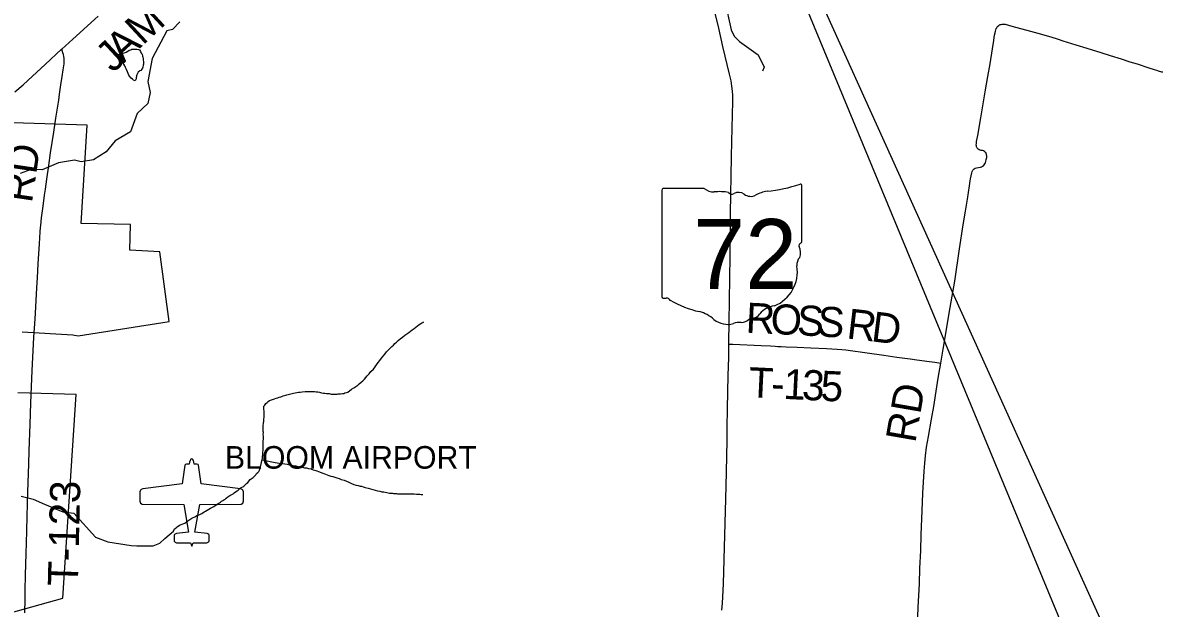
# Model space of a CAD drawing. Extents: x -5.4 to 49.9, y 13.2 to 48.4.
# Drawn here: x 28.445 to 30.593, y 41.82 to 42.924 of the extents above; entities that cross this region are included whole.
import ezdxf

# ---------------------------------------------------------------- set-up
doc = ezdxf.new("R2010")
doc.units = 0
for name, color, linetype in [('GM_X_Airport_Class_3', 7, 'Continuous'), ('GM_X_Airport_Location_Class_3', 7, 'Continuous'), ('GM_X_Airport_Text_Class_3', 7, 'Continuous'), ('GM_X_Corporation', 7, 'Continuous'), ('GM_X_County_Road', 7, 'Continuous'), ('GM_X_County_Road_Text', 7, 'Continuous'), ('GM_X_Minor_Lake', 7, 'Continuous'), ('GM_X_Minor_River', 7, 'Continuous'), ('GM_X_State_Location', 7, 'Continuous'), ('GM_X_State_Route', 7, 'Continuous'), ('GM_X_State_Shield', 7, 'Continuous'), ('GM_X_Township_Road', 7, 'Continuous'), ('GM_X_Township_Road_Text', 7, 'Continuous'), ('SH_Data', 7, 'Continuous')]:
    doc.layers.add(name, color=color, linetype=linetype)

msp = doc.modelspace()

# ---------------------------------------------------------------- linework, layer by layer
at = {"layer": 'GM_X_Airport_Class_3'}
for points in [[(28.7634, 42.1019), (28.7619, 42.1013), (28.7603, 42.099), (28.7592, 42.0956), (28.7586, 42.0921), (28.7535, 42.0921), (28.7515, 42.0915), (28.7505, 42.09), (28.7455, 42.0551), (28.6713, 42.0456), (28.668, 42.0442), (28.6668, 42.0428), (28.6658, 42.0394), (28.6658, 42.0222), (28.667, 42.0185), (28.6701, 42.0162), (28.7483, 42.0157), (28.7574, 41.9637), (28.7344, 41.9611), (28.7331, 41.9608), (28.731, 41.9591), (28.7304, 41.9578), (28.7302, 41.9483), (28.7304, 41.9468), (28.7321, 41.9445), (28.7349, 41.9436), (28.7609, 41.9435), (28.7634, 41.9374)], [(28.7634, 41.9374), (28.7658, 41.9435), (28.7918, 41.9436), (28.7946, 41.9445), (28.7963, 41.9468), (28.7965, 41.9483), (28.7963, 41.9578), (28.7957, 41.9591), (28.7937, 41.9608), (28.7923, 41.9611), (28.7693, 41.9637), (28.7784, 42.0157), (28.8566, 42.0162), (28.8598, 42.0185), (28.8609, 42.0222), (28.8609, 42.0394), (28.8599, 42.0428), (28.8587, 42.0442), (28.8554, 42.0456), (28.7812, 42.0551), (28.7762, 42.09), (28.7752, 42.0915), (28.7732, 42.0921), (28.7681, 42.0921), (28.7675, 42.0956), (28.7664, 42.099), (28.7648, 42.1013), (28.7634, 42.1019)]]:
    msp.add_lwpolyline(points, dxfattribs=at)
at = {"layer": 'GM_X_Airport_Location_Class_3'}
msp.add_line((28.7634, 42.0242), (28.7634, 42.0242), dxfattribs=at)
at = {"layer": 'GM_X_Corporation'}
for points in [[(28.4438, 42.3414), (28.5393, 42.3357), (28.5493, 42.3338), (28.7206, 42.3609), (28.7033, 42.4924), (28.6466, 42.4954), (28.6481, 42.5439), (28.5549, 42.5456), (28.5662, 42.7314), (27.6459, 42.7604)], [(28.349, 41.7916), (28.5206, 41.839), (28.5454, 42.223), (28.4358, 42.2265)]]:
    msp.add_lwpolyline(points, dxfattribs=at)
at = {"layer": 'GM_X_County_Road'}
for points in [[(28.5182, 42.8747), (28.5393, 42.8937), (28.5868, 42.9366)], [(28.43, 42.7941), (28.4454, 42.8076), (28.4633, 42.824), (28.4872, 42.8458), (28.5181, 42.8746), (28.5182, 42.8747)]]:
    msp.add_lwpolyline(points, dxfattribs=at)
at = {"layer": 'GM_X_Minor_Lake'}
msp.add_lwpolyline([(28.625, 42.8648), (28.63, 42.8651), (28.6342, 42.867), (28.6376, 42.8685), (28.6399, 42.8688), (28.6429, 42.8707), (28.6456, 42.8725), (28.6483, 42.8737), (28.6505, 42.8744), (28.6532, 42.8747), (28.6551, 42.8747), (28.657, 42.8747), (28.66, 42.8747), (28.6627, 42.8743), (28.6646, 42.8731), (28.6668, 42.87), (28.6683, 42.8674), (28.6698, 42.8651), (28.6705, 42.8617), (28.6713, 42.8594), (28.672, 42.8571), (28.672, 42.854), (28.6723, 42.8514), (28.6723, 42.8483), (28.6726, 42.8461), (28.6719, 42.8442), (28.6714, 42.8408), (28.6703, 42.8389), (28.6695, 42.837), (28.6676, 42.8347), (28.6653, 42.8336), (28.6626, 42.8314), (28.6595, 42.8253), (28.6591, 42.8234), (28.6587, 42.8215), (28.6583, 42.8185), (28.6568, 42.8151), (28.6537, 42.8162), (28.6515, 42.8182), (28.6492, 42.8201), (28.6462, 42.8235), (28.6447, 42.8258), (28.6436, 42.8285), (28.6421, 42.8319), (28.6403, 42.8361), (28.6388, 42.84), (28.6373, 42.843), (28.6355, 42.8464), (28.6343, 42.8484), (28.625, 42.8648)], dxfattribs=at)
at = {"layer": 'GM_X_Minor_River'}
for points in [[(29.6734, 43.2273), (29.6665, 43.1479), (29.6489, 43.0973), (29.6309, 43.0635), (29.6201, 43.0299), (29.6225, 43.0188), (29.6345, 43.008), (29.6792, 42.9855), (29.7057, 42.9888), (29.7291, 43.0017), (29.7386, 43.003), (29.7495, 42.9983), (29.7686, 42.9649), (29.7802, 42.9111), (29.786, 42.8993), (29.7957, 42.8892), (29.8312, 42.8639), (29.8426, 42.8409), (29.8394, 42.8333)], [(28.7271, 42.9115), (28.7409, 42.9264)], [(28.7271, 42.9115), (28.7166, 42.909), (28.6885, 42.857), (28.6807, 42.8135), (28.6853, 42.7929), (28.6804, 42.7721), (28.6608, 42.7534), (28.6481, 42.7187), (28.619, 42.7017), (28.602, 42.6811), (28.5783, 42.6659), (28.5551, 42.6624), (28.5423, 42.6653), (28.5122, 42.6604), (28.4817, 42.6468), (28.4608, 42.6479), (28.4402, 42.6403)], [(28.9223, 42.2165), (28.9254, 42.2172), (28.9284, 42.2183), (28.9311, 42.2191), (28.9334, 42.2198), (28.9357, 42.2205), (28.9383, 42.2213), (28.9406, 42.222), (28.9429, 42.2224), (28.9452, 42.2231), (28.9478, 42.2238), (28.9501, 42.2246), (28.9528, 42.2253), (28.9555, 42.226), (28.9581, 42.2264), (28.9612, 42.2271), (28.9646, 42.2274), (28.968, 42.2278), (28.9718, 42.2285), (28.9771, 42.2288), (28.9813, 42.2288), (28.9851, 42.2291), (28.9885, 42.2291), (28.9919, 42.229), (28.9949, 42.229), (28.998, 42.2286), (29.001, 42.2282), (29.0044, 42.2274), (29.0082, 42.2266), (29.012, 42.2261), (29.0146, 42.2257), (29.0177, 42.2253), (29.0199, 42.2249), (29.0222, 42.2249), (29.026, 42.2241), (29.0287, 42.2241), (29.0321, 42.224), (29.0351, 42.224), (29.0374, 42.224), (29.0397, 42.2243), (29.0416, 42.2243), (29.0438, 42.2246), (29.0473, 42.225), (29.0499, 42.2253), (29.0518, 42.2265), (29.0549, 42.2272), (29.0575, 42.2279), (29.0644, 42.2332), (29.069, 42.2361), (29.0728, 42.2384), (29.0763, 42.2406), (29.0793, 42.2436), (29.0828, 42.2466), (29.0858, 42.2492), (29.0889, 42.2523), (29.0916, 42.2553), (29.0943, 42.2583), (29.0977, 42.262), (29.1008, 42.2669), (29.1058, 42.2711), (29.1089, 42.2752), (29.112, 42.2793), (29.115, 42.2835), (29.1181, 42.2876), (29.1212, 42.2918), (29.1243, 42.2955), (29.1274, 42.2993), (29.1304, 42.3035), (29.1339, 42.3068), (29.1369, 42.3098), (29.1408, 42.314), (29.1435, 42.3166), (29.1465, 42.3192), (29.1492, 42.3222), (29.1527, 42.3252), (29.1565, 42.3286), (29.1607, 42.3316), (29.1649, 42.335), (29.1687, 42.3376), (29.1726, 42.3402), (29.176, 42.3425), (29.1787, 42.3451), (29.1825, 42.3477), (29.1921, 42.3552), (29.1951, 42.3571), (29.1974, 42.3586), (29.1993, 42.3593), (29.2001, 42.36), (29.1993, 42.3593)], [(28.7126, 41.9518), (28.7288, 41.9657), (28.7308, 41.9698), (28.7338, 41.9721), (28.7357, 41.9739), (28.7403, 41.9769), (28.7453, 41.9788), (28.7487, 41.9799), (28.7506, 41.9806), (28.7529, 41.9825), (28.756, 41.9851), (28.7598, 41.9873), (28.7636, 41.99), (28.769, 41.9926), (28.7732, 41.9948), (28.7766, 41.9963), (28.7789, 41.997), (28.7823, 41.9989), (28.7865, 42.0019), (28.7892, 42.0034), (28.7922, 42.0052), (28.7957, 42.0071), (28.7987, 42.0089), (28.8048, 42.0123), (28.8075, 42.0142), (28.8106, 42.016), (28.8132, 42.0175), (28.8155, 42.019), (28.8174, 42.0205), (28.8197, 42.022), (28.822, 42.0235), (28.8239, 42.0246), (28.8266, 42.0261), (28.8285, 42.028), (28.8316, 42.0302), (28.8354, 42.0325), (28.8392, 42.0347), (28.8415, 42.0358), (28.8434, 42.0377), (28.8457, 42.0396), (28.8488, 42.0418), (28.8511, 42.0429), (28.8541, 42.0459), (28.8568, 42.0478), (28.8595, 42.0493), (28.8618, 42.0504), (28.8664, 42.0557), (28.8694, 42.0575), (28.8733, 42.0628), (28.8771, 42.0654), (28.879, 42.0669), (28.8821, 42.0699), (28.884, 42.0718), (28.8855, 42.0741), (28.8878, 42.0763), (28.8898, 42.0778), (28.8909, 42.0805), (28.8917, 42.0824), (28.8921, 42.0846), (28.8949, 42.0949), (28.8957, 42.0979), (28.8961, 42.1002), (28.8969, 42.1036), (28.8969, 42.1059), (28.8973, 42.1104), (28.8974, 42.1142), (28.8978, 42.1191), (28.8982, 42.1237), (28.8983, 42.1283), (28.8983, 42.1321), (28.8983, 42.1362), (28.8984, 42.1393), (28.8984, 42.1442), (28.8981, 42.148), (28.8985, 42.1514), (28.8982, 42.1537), (28.8982, 42.1568), (28.8982, 42.1594), (28.8982, 42.1625), (28.8983, 42.1655), (28.8987, 42.1678), (28.8987, 42.1704), (28.8991, 42.1723), (28.8992, 42.1765), (28.9, 42.1807), (28.9, 42.1833), (28.9, 42.1852), (28.9, 42.1875), (28.9001, 42.1902), (28.8997, 42.1925), (28.8993, 42.1947), (28.899, 42.197), (28.899, 42.1993), (28.8994, 42.2012), (28.901, 42.2031), (28.9033, 42.2061), (28.9056, 42.2083), (28.9075, 42.2102), (28.9102, 42.2117), (28.9193, 42.215), (28.9223, 42.2165)], [(28.8961, 42.1002), (28.9207, 42.0953), (28.9245, 42.0945), (28.9279, 42.0937), (28.9313, 42.0933), (28.9351, 42.0929), (28.9389, 42.0925), (28.943, 42.0917), (28.9476, 42.0909), (28.9544, 42.0896), (28.9597, 42.0888), (28.9638, 42.0876), (28.968, 42.0868), (28.9722, 42.086), (28.976, 42.0852), (28.9798, 42.0848), (28.9835, 42.084), (28.9877, 42.0828), (28.9922, 42.0812), (28.9972, 42.0797), (29.004, 42.0773), (29.0085, 42.0757), (29.0123, 42.0742), (29.0153, 42.073), (29.0187, 42.0718), (29.0217, 42.0706), (29.0255, 42.0695), (29.0293, 42.0687), (29.0331, 42.0675), (29.0369, 42.0663), (29.041, 42.0647), (29.0452, 42.0632), (29.0508, 42.0616), (29.055, 42.0596), (29.0595, 42.0577), (29.0644, 42.0553), (29.069, 42.0538), (29.0735, 42.0526), (29.0773, 42.0514), (29.0807, 42.0506), (29.0837, 42.0502), (29.0868, 42.0494), (29.0905, 42.0482), (29.0958, 42.0466), (29.1004, 42.0454), (29.1045, 42.0439), (29.1091, 42.0427), (29.1136, 42.0419), (29.1182, 42.0411), (29.1219, 42.0399), (29.1254, 42.0395), (29.1337, 42.0378), (29.1363, 42.0374), (29.1397, 42.0374), (29.1416, 42.037), (29.1439, 42.0366), (29.1466, 42.0366), (29.1492, 42.0365), (29.1515, 42.0361), (29.1538, 42.0361), (29.1561, 42.0361), (29.1583, 42.036), (29.1614, 42.036), (29.1648, 42.036), (29.1693, 42.0359), (29.1731, 42.0359), (29.1765, 42.0358), (29.18, 42.0358), (29.183, 42.0358), (29.1868, 42.0353), (29.1898, 42.0353), (29.1932, 42.0353), (29.1959, 42.0349), (29.1978, 42.0348), (29.1989, 42.0348)], [(28.4419, 42.0314), (28.4646, 42.0258), (28.4861, 42.0164), (28.5203, 42.0022), (28.5412, 41.9996), (28.5822, 41.9545), (28.6052, 41.9455), (28.6494, 41.9387), (28.6597, 41.9378), (28.6908, 41.9381), (28.703, 41.9432), (28.7126, 41.9518)]]:
    msp.add_lwpolyline(points, dxfattribs=at)
at = {"layer": 'GM_X_State_Route'}
msp.add_lwpolyline([(29.7628, 41.8164), (29.7641, 41.8295), (29.7648, 41.8419), (29.7656, 41.8661), (29.7705, 42.0268), (29.7713, 42.0761), (29.772, 42.1085), (29.7725, 42.1352), (29.7729, 42.1607), (29.7736, 42.1967), (29.7749, 42.2594), (29.7756, 42.293), (29.776, 42.3185), (29.7761, 42.3216), (29.7766, 42.3595), (29.7783, 42.4844), (29.7788, 42.5645), (29.7808, 42.6713), (29.7816, 42.7005), (29.7836, 42.7757), (29.7834, 42.7875), (29.7828, 42.7956), (29.7817, 42.8049), (29.78, 42.8148), (29.7774, 42.8276), (29.7648, 42.8795), (29.7568, 42.914), (29.7422, 42.9764)], dxfattribs=at)
at = {"layer": 'GM_X_State_Shield'}
for p, q in [((29.6497, 42.6084), (29.6497, 42.4083)), ((29.7296, 42.6118), (29.6523, 42.6118)), ((29.9134, 42.5121), (29.9134, 42.6168)), ((29.9134, 42.5121), (29.9134, 42.5121))]:
    msp.add_line(p, q, dxfattribs=at)
for centre, radius, start, end in [((29.8195, 42.8847), 0.2796, 275.8445, 288.9065), ((29.9105, 42.6172), 0.00294, 351.8621, 97.738), ((29.6528, 42.6088), 0.00305, 98.1301, 188.1301), ((29.7479, 42.6351), 0.0296, 231.6195, 271.1119), ((29.7578, 42.4995), 0.1064, 80.4867, 94.9883), ((29.7819, 42.6098), 0.00855, 219.7921, 297.1024), ((29.7945, 42.5867), 0.0178, 54.4667, 119.1411), ((29.8174, 42.6184), 0.0214, 233.8562, 294.8282), ((29.8552, 42.5507), 0.0563, 97.3462, 120.7689), ((29.9103, 42.5117), 0.00314, 289.6038, 7.7341), ((29.9127, 42.5044), 0.00454, 107.944, 210.337), ((29.8838, 42.4912), 0.0273, 340.033, 23.6496), ((29.9239, 42.4683), 0.0198, 136.8065, 186.9296), ((29.8352, 42.455), 0.0699, 292.3089, 8.9858), ((29.6528, 42.4078), 0.00308, 171.9584, 258.3066), ((29.6533, 42.4283), 0.0235, 267.339, 280.6039), ((29.6581, 42.3967), 0.00848, 29.7484, 93.2717), ((29.7651, 42.5765), 0.2019, 240.4129, 257.1985), ((29.8646, 42.3521), 0.0383, 94.4031, 142.5768), ((29.7049, 42.3184), 0.0632, 47.1842, 75.836), ((29.7733, 42.3957), 0.0401, 230.7004, 286.2918), ((29.7964, 42.3265), 0.0329, 85.6951, 111.2099), ((29.7994, 42.3807), 0.0214, 268.777, 315.5493), ((29.8187, 42.3614), 0.00601, 65.7517, 132.6484), ((29.8161, 42.3889), 0.0226, 282.8732, 323.2771)]:
    msp.add_arc(centre, radius, start, end, dxfattribs=at)
at = {"layer": 'GM_X_Township_Road'}
for points in [[(30.1756, 42.2825), (30.1801, 42.3087), (30.1832, 42.3271), (30.1869, 42.3504), (30.1933, 42.3872), (30.2018, 42.4368), (30.2039, 42.4503), (30.2087, 42.4847), (30.2106, 42.4982), (30.2178, 42.5436), (30.222, 42.5693), (30.2257, 42.592), (30.2298, 42.6172), (30.2311, 42.6264), (30.2317, 42.63), (30.2326, 42.6356), (30.234, 42.6416), (30.2347, 42.644), (30.2358, 42.6462), (30.237, 42.6476), (30.2383, 42.6489), (30.2404, 42.6501), (30.2428, 42.651), (30.2502, 42.6523), (30.2523, 42.653), (30.2543, 42.6538), (30.2558, 42.6549), (30.2572, 42.6563), (30.2584, 42.6582), (30.2595, 42.6603), (30.2604, 42.663), (30.2613, 42.6668), (30.2621, 42.6705), (30.2622, 42.6729), (30.2619, 42.6759), (30.2612, 42.6779), (30.2603, 42.6795), (30.2593, 42.6807), (30.2577, 42.6819), (30.2563, 42.6826), (30.2543, 42.6833), (30.2519, 42.6838), (30.2478, 42.685), (30.2459, 42.686), (30.2448, 42.687), (30.2438, 42.6884), (30.2432, 42.6894), (30.2427, 42.6907), (30.2426, 42.6924), (30.2424, 42.6942), (30.2425, 42.6967), (30.243, 42.7004), (30.2452, 42.712), (30.2508, 42.7451), (30.2593, 42.7941), (30.2643, 42.8228), (30.2685, 42.8473), (30.2729, 42.8756), (30.2754, 42.8909), (30.2763, 42.8964), (30.277, 42.9013), (30.2778, 42.9057), (30.2784, 42.9087), (30.2791, 42.9112), (30.28, 42.9134), (30.2809, 42.9151), (30.282, 42.9168), (30.2832, 42.9182), (30.2848, 42.9195), (30.2861, 42.9203), (30.2875, 42.921), (30.2891, 42.9215), (30.2909, 42.9219), (30.2925, 42.9221), (30.2946, 42.922), (30.2968, 42.9216), (30.3097, 42.9181), (30.3444, 42.9084), (30.3582, 42.9048), (30.3827, 42.8978), (30.3969, 42.8933), (30.4058, 42.8904), (30.4301, 42.8828), (30.4508, 42.8764), (30.4769, 42.8682), (30.4947, 42.8626), (30.5154, 42.8562), (30.532, 42.8509), (30.5456, 42.8467), (30.568, 42.8394), (30.5775, 42.8363), (30.5823, 42.8349), (30.5855, 42.8338)], [(28.4485, 41.8113), (28.4492, 41.8374), (28.4496, 41.8529), (28.4503, 41.8834), (28.4513, 41.9225), (28.4524, 41.9654), (28.4533, 41.994), (28.4546, 42.0393), (28.4563, 42.0927), (28.4569, 42.1169), (28.4585, 42.1673), (28.4602, 42.207), (28.4615, 42.2387), (28.4626, 42.2678), (28.4659, 42.3312), (28.4679, 42.3653), (28.4693, 42.3889), (28.4716, 42.4248), (28.4726, 42.4434), (28.4741, 42.4695), (28.4764, 42.5073), (28.4778, 42.5303), (28.4784, 42.5383), (28.4788, 42.542), (28.4803, 42.5568), (28.4813, 42.5655), (28.4831, 42.5784), (28.486, 42.5993), (28.4876, 42.6104), (28.4902, 42.6295), (28.4939, 42.6553), (28.4972, 42.6793), (28.5034, 42.7179), (28.5074, 42.7443), (28.5107, 42.7671), (28.5126, 42.7787), (28.5143, 42.7898), (28.5168, 42.8076), (28.5191, 42.8229), (28.5211, 42.8358), (28.5227, 42.8469), (28.5231, 42.8524), (28.5229, 42.8574), (28.5223, 42.8611), (28.5214, 42.8647), (28.5204, 42.8679), (28.5182, 42.8747)], [(30.5855, 42.8338), (30.5869, 42.8333), (30.5898, 42.8325), (30.5914, 42.8321), (30.5939, 42.8319)], [(29.776, 42.3185), (29.7832, 42.3184), (29.8371, 42.3158), (29.8545, 42.3148), (29.8631, 42.3143), (29.8681, 42.314), (29.8743, 42.3137), (29.8842, 42.3134), (29.9047, 42.3127), (29.9302, 42.3116), (29.96, 42.3103), (29.9804, 42.3089), (29.9891, 42.3081), (29.9965, 42.3074), (30.0094, 42.3058), (30.0278, 42.3033), (30.037, 42.3019), (30.0683, 42.2974), (30.0929, 42.2937), (30.1175, 42.2903), (30.1304, 42.2885), (30.1543, 42.2854), (30.1641, 42.284), (30.1756, 42.2825)], [(30.1316, 41.7864), (30.1331, 41.8224), (30.1352, 41.8664), (30.1362, 41.8956), (30.1376, 41.9285), (30.1388, 41.9595), (30.1405, 42.0036), (30.1419, 42.0371), (30.1441, 42.0787), (30.1451, 42.0936), (30.1466, 42.1078), (30.1487, 42.1238), (30.1521, 42.144), (30.1581, 42.177), (30.1621, 42.2009), (30.168, 42.2377), (30.1706, 42.2543), (30.1756, 42.2825)]]:
    msp.add_lwpolyline(points, dxfattribs=at)
at = {"layer": 'SH_Data'}
msp.add_lwpolyline([(31.0729, 40.4803), (29.5617, 43.8236), (31.0729, 40.1733)], close=True, dxfattribs=at)

# ---------------------------------------------------------------- texts
at = {"layer": 'GM_X_Airport_Text_Class_3'}
msp.add_text('BLOOM AIRPORT', height=0.042614, rotation=0, dxfattribs=at).set_placement((28.8259, 42.0834))
at = {"layer": 'GM_X_County_Road_Text'}
for s, rotation, p in [('M', 42.8191, (28.6709, 42.8807)), ('A', 42.8204, (28.6343, 42.8467)), ('J', 42.8213, (28.6147, 42.8286))]:
    msp.add_text(s, height=0.0568, rotation=rotation, dxfattribs=at).set_placement(p)
at = {"layer": 'GM_X_State_Location'}
for s in ['s', 'r']:
    msp.add_text(s, height=0.000189, dxfattribs=at).set_placement((29.7786, 42.495))
msp.add_text('72', height=0.000189, rotation=0, dxfattribs=at).set_placement((29.7309, 42.4812))
at = {"layer": 'GM_X_State_Shield'}
msp.add_text('72', height=0.13184, dxfattribs=at).set_placement((29.7087, 42.4224))
at = {"layer": 'GM_X_Township_Road_Text'}
for s, height, rotation, p in [('RD', 0.05682, 81.5878, (28.462, 42.5832)), ('R', 0.0568, 357.259, (29.807, 42.34)), ('O', 0.0568, 357.2584, (29.8536, 42.3377)), ('S', 0.0568, 357.1907, (29.9035, 42.3353)), ('S', 0.0568, 356.0295, (29.9415, 42.3335)), ('R', 0.0568, 353.3499, (29.9965, 42.3293)), ('D', 0.0568, 352.823, (30.0427, 42.3239)), ('T', 0.0568, 357.2262, (29.8121, 42.2183)), ('1', 0.0568, 357.2426, (29.8779, 42.2151)), ('3', 0.0568, 357.2676, (29.9129, 42.2134)), ('5', 0.0568, 357.3729, (29.948, 42.2117)), ('-', 0.0568, 357.2378, (29.8546, 42.2162)), ('RD', 0.05682, 80.1399, (30.1273, 42.1306)), ('T-123', 0.05682, 88.6102, (28.5487, 41.8618))]:
    msp.add_text(s, height=height, rotation=rotation, dxfattribs=at).set_placement(p)

doc.saveas('drawing.dxf')
